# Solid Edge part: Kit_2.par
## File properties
Sűrűség: 0,000 kg/m^3
Pontosság: 0,990
Author: bmolnar
Last saved by: bmolnar
Revision: 77
Username: bmolnar
Dokumentum tartalom típus: 0
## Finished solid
Body 1: solid body, 21 faces, 37 edges, 27 vertices.
  Faces by surface: cylinder 10, plane 9, cone 1, torus 1
  Edges by curve: circle 23, line 14
Bounding box of the edges (mm; curved faces can reach further): 44.500 x 44.125 x 4.250, from (-22.25, -20.85, 0.5) to (22.25, 23.275, 4.75).
Cylindrical faces by radius (mm): R1.25 x2, R2.5 x4, R13.95 x1, R19.175 x1, R20.85 x1, R22.25 x1
Conical faces (half-angle, radius in mm at the cone's reference point): 45 deg R13.7 x1
Toroidal faces (ring radius, tube radius in mm): R14.75 r0.8 x1
Planar faces by outward normal: +z 2, -z 5, oblique 2
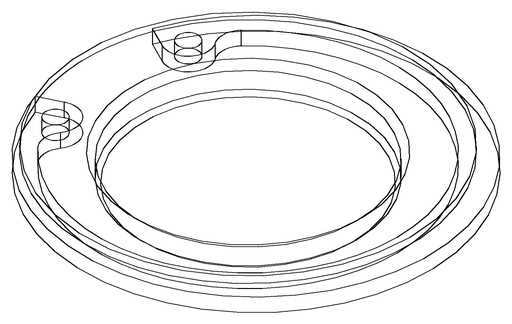
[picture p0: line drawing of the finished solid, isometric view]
